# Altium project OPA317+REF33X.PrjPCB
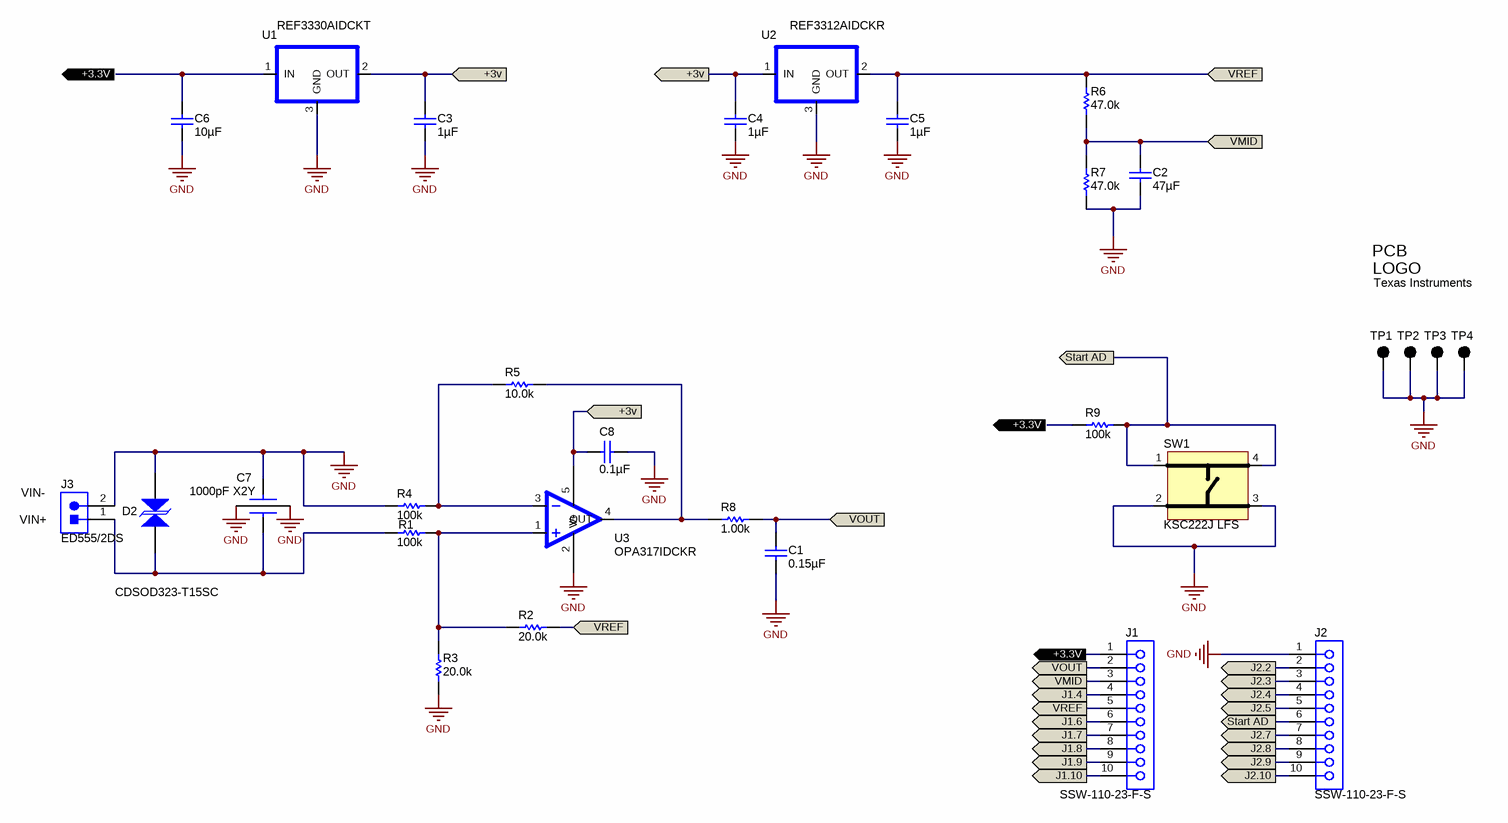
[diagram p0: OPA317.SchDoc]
CopyrightYear: 2014; PCB_Layout: Janet Sun; PCB_Rev: E1; PRJ_Customer: TI Precision Designs; PRJ_Engineer: Janet Sun, Collin Wells; PRJ_Number: TIPD154; PRJ_Title: TIPD154; SCH_Rev: E1; TechSupport: http://www.ti.com/support
1 sheet, 30 parts. Net scope: flat (ports and power ports of the same name join across sheets).
Board file: OPA317.PcbDoc

## Sheet OPA317.SchDoc: TIPD154
size 431 x 279 mm; Date: Not shown in title block; ApprovedBy: Not shown in title block; CheckedBy: Not shown in title block; Author: Not shown in title block; CompanyName: Not shown in title block; DrawnBy: Janet Sun, Collin Wells; Engineer: Not shown in title block; Organization: Not shown in title block; Address1: Not shown in title block; Address2: Not shown in title block; Address3: Not shown in title block; Address4: Not shown in title block; DocumentNumber: 1; Revision: Use project parameter SCH_Rev; SheetNumber: 1; SheetTotal: 1; PageSetup: Record=PageOptions|CenterHorizontal=True|CenterVertical=True|PrintScale=0.62|XCorrection=1.00|YCorrection=1.00|PrintKind=0|BorderSize=5000000|LeftOffset=0|BottomOffset=0|Orientation=2|PaperLength=1000|PaperWidth=1000|Scale=100|PaperSource=15|PrintQuality=600|MediaType=1|DitherType=10|PaperKind=Letter|PrintScaleMode=1

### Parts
C1  ValueDisplayed: 0.15µF  [0603]  (hidden comment: GRM188R71C154KA01D)
C2  ValueDisplayed: 47µF  [0603]  (hidden comment: GRM188R60J476M)
C3  ValueDisplayed: 1µF  [0603]  (hidden comment: C1608X7R1C105K)
C4  ValueDisplayed: 1µF  [0603]  (hidden comment: C1608X7R1C105K)
C5  ValueDisplayed: 1µF  [0603]  (hidden comment: C1608X7R1C105K)
C6  ValueDisplayed: 10µF  [1206]  (hidden comment: C3216X7R1C106M)
C7  1000pF X2Y  [X2Y_0603]
C8  ValueDisplayed: 0.1µF  [0603]  (hidden comment: GRM188R71H104KA93D)
D2  CDSOD323-T15SC  [sod-323]
J1  SSW-110-23-F-S  [CONN_SSW-110-23-F-S]
J2  SSW-110-23-F-S  [CONN_SSW-110-23-F-S]
J3  ED555/2DS  [TERM_BLK_ED555-2DS]
Logo?  Texas Instruments  [TI_Stacked_Overlay_Small]  (no BOM)
R1  value 100k  [0603]  (hidden comment: RG1608P-104-B-T5)
R2  value 20.0k  [0603]  (hidden comment: RG1608P-203-B-T5)
R3  value 20.0k  [0603]  (hidden comment: RG1608P-203-B-T5)
R4  value 100k  [0603]  (hidden comment: RG1608P-104-B-T5)
R5  value 10.0k  [0603]  (hidden comment: RG1608P-103-B-T5)
R6  value 47.0k  [0603]  (hidden comment: RG1608P-473-B-T5)
R7  value 47.0k  [0603]  (hidden comment: RG1608P-473-B-T5)
R8  value 1.00k  [0603]  (hidden comment: RT0603BRD071KL)
R9  value 100k  [0603]  (hidden comment: RG1608P-104-B-T5)
SW1  KSC222J LFS  [KSC222J LFS]
TP1  5001  [Keystone5001]  (value not drawn)
TP2  5001  [Keystone5001]  (value not drawn)
TP3  5001  [Keystone5001]  (value not drawn)
TP4  5001  [Keystone5001]  (value not drawn)
U1  REF3330AIDCKT  [SC70]
U2  REF3312AIDCKR  [SC70]
U3  OPA317IDCKR  [SC-70-5]

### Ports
+3.3V, +3v, J1.4, J1.6, J1.7, J1.8, J1.9, J1.10, J2.2, J2.3, J2.4, J2.5, J2.7, J2.8, J2.9, J2.10, Start AD, VMID, VOUT, VREF

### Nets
GND: C1.2 C2.2 C3.2 C4.2 C5.2 C6.2 C7.1 C7.3 C7.4 C8.2 D2.1 J2.1 J3.2 R3.1 R4.1 R7.1 SW1.2 SW1.3 TP1.1 TP2.1 TP3.1 TP4.1 U1.3(GND) U2.3(GND) U3.2(V-)
+3.3V: C6.1 J1.1 R9.2 U1.1(IN) ; port +3.3V
+3v: C3.1 C4.1 C8.1 U1.2(OUT) U2.1(IN) U3.5(V+) ; port +3v
J1.4: J1.4 ; port J1.4
J1.6: J1.6 ; port J1.6
J1.7: J1.7 ; port J1.7
J1.8: J1.8 ; port J1.8
J1.9: J1.9 ; port J1.9
J1.10: J1.10 ; port J1.10
J2.2: J2.2 ; port J2.2
J2.3: J2.3 ; port J2.3
J2.4: J2.4 ; port J2.4
J2.5: J2.5 ; port J2.5
J2.7: J2.7 ; port J2.7
J2.8: J2.8 ; port J2.8
J2.9: J2.9 ; port J2.9
J2.10: J2.10 ; port J2.10
Start AD: J2.6 R9.1 SW1.1 SW1.4 ; port Start AD
VMID: C2.1 J1.3 R6.1 R7.2 ; port VMID
VOUT: C1.1 J1.2 R8.2 ; port VOUT
VREF: C5.1 J1.5 R2.2 R6.2 U2.2(OUT) ; port VREF
NetC7_2: C7.2 D2.2 J3.1 R1.1
NetR1_2: R1.2 R2.1 R3.2 U3.1
NetR4_2: R4.2 R5.1 U3.3
NetR5_2: R5.2 R8.1 U3.4(OUT)

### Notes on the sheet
- (near J3) VIN-
- (near J3) VIN+

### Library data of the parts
C1 = GRM188R71C154KA01D: CAP, CERM, 0.15uF, 16V, +/-10%, X7R, 0603; Manufacturer: MuRata; Polarized: N; CompType: Capacitor; U/M: EA; Cap_F: 0.00000015; Tolerance_%: 10; Value1: Unknown; VDC_V: 16; TaMin_C: -55; TaMax_C: 125
C2 = GRM188R60J476M: CAP, CERM, 47uF, 6.3V, +/-20%, X5R, 0603; Manufacturer: MuRata; Polarized: N; CompType: Capacitor; U/M: EA; Cap_F: 0.000047; Tolerance_%: 20; Value1: Unknown; VDC_V: 6.3; TaMin_C: -55; TaMax_C: 85
C3-C5 = C1608X7R1C105K: CAP, CERM, 1uF, 16V, +/-10%, X7R, 0603; Manufacturer: TDK; Polarized: N; CompType: Capacitor; U/M: EA; Cap_F: 0.000001; Tolerance_%: 10; ESR_Ohm: 0.0057; Value1: 0.0057 ohm; VDC_V: 16; TaMin_C: -55; TaMax_C: 125
C6 = C3216X7R1C106M: CAP, CERM, 10uF, 16V, +/-20%, X7R, 1206; Manufacturer: TDK; Polarized: N; CompType: Capacitor; U/M: EA; Cap_F: 0.00001; Tolerance_%: 20; ESR_Ohm: 0.0046; Value1: 0.0046 ohm; VDC_V: 16; TaMin_C: -55; TaMax_C: 125
C7 = X2Y Capacitor: CAP CER 1000PF 50V 20% X7R 0603; Manufacturer: Johanson Dielectrics Inc; PartNumber: 500X14W102MV4T; U/M: EA; TaMax_C: 125; TaMin_C: -55; Tolerance%: +/-20; Value2: 16V
C8 = GRM188R71H104KA93D: CAP, CERM, 0.1uF, 50V, +/-10%, X7R, 0603; Manufacturer: MuRata; Polarized: N; CompType: Capacitor; U/M: EA; Cap_F: 0.0000001; Tolerance_%: 10; VDC_V: 50; TaMin_C: -55; TaMax_C: 125
D2 = SMAJ15CA: DIODE TVS ARRAY 15V SOD323; Manufacturer: Bourns; SymbolVersion: use current date i.e. 2008-05-20; SymbolCreator: Use LDAP id; U/M: EA, IN, or GM
J1 J2 = SSW-110-23-F-S: Connector, Receptacle, 100mil, 10x1, Gold plated, TH; Manufacturer: Samtec, Inc.; SymbolCreator: a0411947; U/M: EA
J3 = ED555/2DS: Terminal Block, 6A, 3.5mm Pitch, 2-Pos, TH; Manufacturer: On-Shore Technology; SymbolCreator: a0412235; CompType: Connector; U/M: EA
Logo? = TI_Logo: Texas Instrument Corporate Signature; SymbolCreator: a0412235
R1 R4 R9 = RG1608P-104-B-T5: RES, 100k ohm, 0.1%, 0.1W, 0603; Manufacturer: Susumu Co Ltd; CompType: Resistor; Res_ohm: 100000; Tolerance_%: 0.1; VDC_V: 75; TempCo: 25 ppm/C; EIA_Code: E192; U/M: EA
R2 R3 = RG1608P-203-B-T5: RES, 20.0k ohm, 0.1%, 0.1W, 0603; Manufacturer: Susumu Co Ltd; CompType: Resistor; Res_ohm: 20000; Value_Code: 20k0; Tolerance_%: 0.1; VDC_V: 75; TempCo: 25 ppm/C; EIA_Code: E192; U/M: EA
R5 = RG1608P-103-B-T5: RES, 10.0k ohm, 0.1%, 0.1W, 0603; Manufacturer: Susumu Co Ltd; CompType: Resistor; Res_ohm: 10000; Value_Code: 10k0; Tolerance_%: 0.1; VDC_V: 75; TempCo: 25 ppm/C; EIA_Code: E192; U/M: EA
R6 R7 = RG1608P-473-B-T5: RES, 47.0k ohm, 0.1%, 0.1W, 0603; Manufacturer: Susumu Co Ltd; CompType: Resistor; Res_ohm: 47000; Value_Code: 47k0; Tolerance_%: 0.1; VDC_V: 75; TempCo: 25 ppm/C; EIA_Code: E192; U/M: EA
R8 = RT0603BRD071KL: RES, 1.00k ohm, 0.1%, 0.1W, 0603; Manufacturer: Yageo America; CompType: Resistor; Res_ohm: 1000; Value_Code: 1k00; Tolerance_%: 0.1; VDC_V: 75; TempCo: 25 ppm/C; EIA_Code: E192; U/M: EA
SW1 = KSC222J LFS: SWITCH TACTILE SPST-NO 0.05A 32V; Manufacturer: C&K Components; Switch Function: Off-Mom; Actuator Orientation: Top Actuated; Ingress Protection: IP67 - Dust Tight, Waterproof; Operating Force: 160gf; Outline: 6.20mm x 6.20mm; Illumination: Non-Illuminated; Contact Rating @ Voltage: 0.05A @ 32VDC; Actuator Height off PCB, from Pins: 3.50mm; Actuator Type: Standard; Mechanical Life: 1,000,000 Cycles; Switch Travel: 0.35mm
TP1-TP4 = 5001: Test Point, Miniature, Black, TH; Manufacturer: Keystone; CompType: Test Point Loop; U/M: EA
U1 U2 = REF33XXAIDBZ: IC, 30 ppm/°C, 3.9 µA  xx-Voltage Reference; Manufacturer: TI; Alternate Manufacturer: None; Area: 30600
U3 = OPA349SA: Manufacturer: TI; Alternate Manufacturer: None; Area: 31500

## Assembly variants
001: not fitted FID1 FID2 FID3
